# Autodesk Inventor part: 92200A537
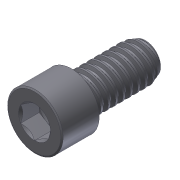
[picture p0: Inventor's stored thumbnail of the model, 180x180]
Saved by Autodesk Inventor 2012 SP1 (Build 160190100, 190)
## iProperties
Created: 2012-03
Part Number: 92200A537
Material: Stainless Steel
Document SubType Name: Modeling
Designer: jdh
Mass: 5.81496 g
Surface Area: 7.09572 cm^2
Volume: 0.719673 cm^3
Density: 8.08 g/cm^3
Author: jdh
Translation Standard: STEP AP203
FileName: 92200A537.step
PreProcessor: SolidWorks 2003314
PostProcessor: Build: 190, Release: 2012 SP1 - Date: Mon 08/08/2011
Sent Units: inch
Uncertainty: 1e-05
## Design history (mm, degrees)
node "92200A5371"
node "NONE"
node "Base1"
